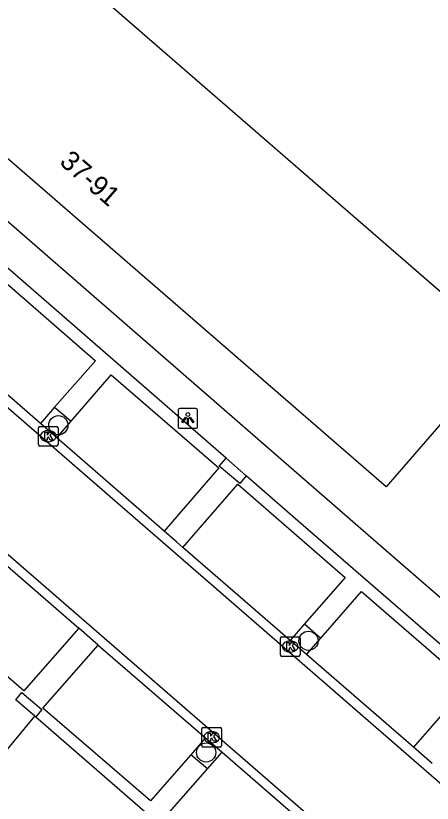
# Model space of a CAD drawing. Extents: x 161882 to 162509, y 381687 to 382379.
# Drawn here: x 162016.16 to 162037.39, y 382160.76 to 382200.83 of the extents above; entities that cross this region are included whole.
import ezdxf

# ---------------------------------------------------------------- set-up
doc = ezdxf.new("R2010")
doc.units = 0
for name, color, linetype in [('IMGEO_Boom', 7, 'Continuous'), ('IMGEO_Kolk', 7, 'Continuous'), ('IMGEO_Lichtpunt', 7, 'Continuous'), ('IMGEO_Pand', 7, 'Continuous'), ('IMGEO_Pand_nummerreeks', 7, 'Continuous'), ('IMGEO_Parkeervlak_open', 7, 'Continuous'), ('IMGEO_Rijbaan_lokaal_open', 7, 'Continuous'), ('IMGEO_Voetpad_op_trap', 7, 'Continuous'), ('IMGEO_Voetpad_open', 7, 'Continuous')]:
    doc.layers.add(name, color=color, linetype=linetype)

msp = doc.modelspace()

# ---------------------------------------------------------------- linework, layer by layer
at = {"layer": 'IMGEO_Boom'}
for centre in [(162018.336, 382179.992), (162031.081, 382169.028), (162025.866, 382163.347)]:
    msp.add_circle(centre, 0.489, dxfattribs=at)
at = {"layer": 'IMGEO_Kolk'}
for p, q in [((162017.317, 382179.01), (162017.317, 382179.862)), ((162017.392, 382179.936), (162018.244, 382179.936)), ((162018.318, 382179.862), (162018.318, 382179.01)), ((162017.805, 382179.716), (162017.83, 382179.716)), ((162017.828, 382179.156), (162017.803, 382179.156)), ((162018.244, 382178.936), (162017.392, 382178.936)), ((162029.647, 382168.31), (162029.647, 382169.162)), ((162029.722, 382169.236), (162030.574, 382169.236)), ((162030.648, 382169.162), (162030.648, 382168.31)), ((162030.135, 382169.016), (162030.16, 382169.016)), ((162030.574, 382168.236), (162029.722, 382168.236)), ((162030.158, 382168.456), (162030.133, 382168.456)), ((162025.719, 382164.62), (162026.571, 382164.62)), ((162025.644, 382163.694), (162025.644, 382164.546)), ((162026.132, 382164.4), (162026.157, 382164.4)), ((162026.645, 382164.546), (162026.645, 382163.694)), ((162026.155, 382163.84), (162026.13, 382163.84)), ((162026.571, 382163.62), (162025.719, 382163.62))]:
    msp.add_line(p, q, dxfattribs=at)
for points in [[(162017.317, 382179.01), (162017.317, 382179.862)], [(162017.392, 382179.936), (162018.244, 382179.936)], [(162018.318, 382179.862), (162018.318, 382179.01)], [(162017.638, 382179.636), (162017.761, 382179.636), (162017.761, 382179.485), (162017.891, 382179.636), (162018.055, 382179.636), (162017.909, 382179.485), (162018.062, 382179.236), (162017.91, 382179.236), (162017.825, 382179.4), (162017.761, 382179.333), (162017.761, 382179.236), (162017.638, 382179.236), (162017.638, 382179.636)], [(162018.244, 382178.936), (162017.392, 382178.936)], [(162029.647, 382168.31), (162029.647, 382169.162)], [(162029.722, 382169.236), (162030.574, 382169.236)], [(162030.648, 382169.162), (162030.648, 382168.31)], [(162029.968, 382168.936), (162030.091, 382168.936), (162030.091, 382168.785), (162030.221, 382168.936), (162030.385, 382168.936), (162030.239, 382168.785), (162030.392, 382168.536), (162030.24, 382168.536), (162030.155, 382168.7), (162030.091, 382168.633), (162030.091, 382168.536), (162029.968, 382168.536), (162029.968, 382168.936)], [(162030.574, 382168.236), (162029.722, 382168.236)], [(162025.719, 382164.62), (162026.571, 382164.62)], [(162025.644, 382163.694), (162025.644, 382164.546)], [(162025.965, 382164.32), (162026.088, 382164.32), (162026.088, 382164.169), (162026.218, 382164.32), (162026.382, 382164.32), (162026.236, 382164.169), (162026.389, 382163.92), (162026.237, 382163.92), (162026.152, 382164.084), (162026.088, 382164.017), (162026.088, 382163.92), (162025.965, 382163.92), (162025.965, 382164.32)], [(162026.645, 382164.546), (162026.645, 382163.694)], [(162026.571, 382163.62), (162025.719, 382163.62)]]:
    msp.add_lwpolyline(points, dxfattribs=at)
for centre, start, end in [((162017.394, 382179.86), 91.552, 178.448), ((162017.394, 382179.86), 91.552, 178.448), ((162018.242, 382179.86), 1.552, 88.448), ((162018.242, 382179.86), 1.552, 88.448), ((162017.394, 382179.012), 181.552, 268.448), ((162017.394, 382179.012), 181.552, 268.448), ((162018.242, 382179.012), 271.552, 358.448), ((162018.242, 382179.012), 271.552, 358.448), ((162029.724, 382169.16), 91.552, 178.448), ((162029.724, 382169.16), 91.552, 178.448), ((162030.572, 382169.16), 1.552, 88.448), ((162030.572, 382169.16), 1.552, 88.448), ((162029.724, 382168.312), 181.552, 268.448), ((162029.724, 382168.312), 181.552, 268.448), ((162030.572, 382168.312), 271.552, 358.448), ((162030.572, 382168.312), 271.552, 358.448), ((162025.721, 382164.544), 91.552, 178.448), ((162025.721, 382164.544), 91.552, 178.448), ((162026.569, 382164.544), 1.552, 88.448), ((162026.569, 382164.544), 1.552, 88.448), ((162025.721, 382163.696), 181.552, 268.448), ((162025.721, 382163.696), 181.552, 268.448), ((162026.569, 382163.696), 271.552, 358.448), ((162026.569, 382163.696), 271.552, 358.448)]:
    msp.add_arc(centre, 0.0765, start, end, dxfattribs=at)
for centre, major_axis, ratio, start_param, end_param in [((162017.804, 382179.436), (-0.387, 0.002), 0.722429, 4.712389, 7.853982), ((162017.829, 382179.436), (-0.39, 0.002), 0.717154, 1.570796, 4.712389), ((162030.134, 382168.736), (-0.387, 0.002), 0.722429, 4.712389, 7.853982), ((162030.159, 382168.736), (-0.39, 0.002), 0.717154, 1.570796, 4.712389), ((162026.131, 382164.12), (-0.387, 0.002), 0.722429, 4.712389, 7.853982), ((162026.156, 382164.12), (-0.39, 0.002), 0.717154, 1.570796, 4.712389)]:
    msp.add_ellipse(centre, major_axis=major_axis, ratio=ratio, start_param=start_param, end_param=end_param, dxfattribs=at)
at = {"layer": 'IMGEO_Lichtpunt'}
for p, q in [((162024.432, 382180.744), (162024.432, 382179.937)), ((162024.432, 382180.744), (162024.432, 382179.937)), ((162025.334, 382180.839), (162024.526, 382180.839)), ((162025.334, 382180.839), (162024.526, 382180.839)), ((162025.428, 382179.937), (162025.428, 382180.744)), ((162025.428, 382179.937), (162025.428, 382180.744)), ((162024.526, 382179.843), (162025.334, 382179.843)), ((162024.526, 382179.843), (162025.334, 382179.843))]:
    msp.add_line(p, q, dxfattribs=at)
for points in [[(162024.806, 382180.408), (162024.845, 382180.38), (162024.657, 382180.118), (162024.619, 382180.145), (162024.806, 382180.408)], [(162024.908, 382180.36), (162024.955, 382180.36), (162024.955, 382180.038), (162024.908, 382180.038), (162024.908, 382180.36)], [(162025.018, 382180.38), (162025.056, 382180.407), (162025.243, 382180.145), (162025.204, 382180.117), (162025.018, 382180.38)]]:
    msp.add_lwpolyline(points, dxfattribs=at)
msp.add_circle((162024.931, 382180.542), 0.0994, dxfattribs=at)
for centre, start, end in [((162024.526, 382180.744), 90, 180), ((162024.526, 382180.744), 90, 180), ((162025.334, 382180.744), 0, 90), ((162025.334, 382180.744), 0, 90), ((162024.526, 382179.937), 180, 270), ((162024.526, 382179.937), 180, 270), ((162025.334, 382179.937), 270, 0), ((162025.334, 382179.937), 270, 360)]:
    msp.add_arc(centre, 0.0946, start, end, dxfattribs=at)
at = {"layer": 'IMGEO_Pand'}
msp.add_lwpolyline([(162010.443, 382210.514), (162014.282, 382207.186), (162018.121, 382203.859), (162041.023, 382184.008), (162041.152, 382183.891), (162035.04, 382176.852), (162004.335, 382203.455)], dxfattribs=at)
at = {"layer": 'IMGEO_Parkeervlak_open'}
for points in [[(162018.145, 382180.908), (162017.419, 382180.08)], [(162018.255, 382179.355), (162018.982, 382180.193)], [(162030.882, 382169.882), (162030.15, 382169.045)], [(162030.974, 382168.332), (162031.705, 382169.163)], [(162025.835, 382164.089), (162025.078, 382163.223)], [(162025.936, 382162.505), (162026.682, 382163.354)]]:
    msp.add_lwpolyline(points, dxfattribs=at)
at = {"layer": 'IMGEO_Rijbaan_lokaal_open'}
for points in [[(162004.578, 382191.195), (162004.274, 382190.846), (162005.488, 382189.784), (162024.055, 382173.714), (162042.512, 382157.689)], [(162036.646, 382154.691), (162036.967, 382155.028), (162001.899, 382185.403), (162000.705, 382186.422), (162000.438, 382186.65), (162000.135, 382186.301)], [(162017.419, 382180.08), (162011.989, 382184.789)], [(162018.255, 382179.355), (162017.419, 382180.08)], [(162023.729, 382174.608), (162018.255, 382179.355)], [(162013.934, 382174.385), (162019.379, 382169.666)], [(162024.683, 382173.78), (162024.348, 382174.07), (162023.729, 382174.608)], [(162030.15, 382169.045), (162024.683, 382173.78)], [(162020.364, 382168.811), (162019.379, 382169.666)], [(162030.974, 382168.332), (162030.15, 382169.045)], [(162020.364, 382168.811), (162025.835, 382164.089)], [(162036.426, 382163.61), (162030.974, 382168.332)], [(162025.835, 382164.089), (162026.682, 382163.354)], [(162037.387, 382162.778), (162036.426, 382163.61)], [(162026.682, 382163.354), (162032.109, 382158.646)]]:
    msp.add_lwpolyline(points, dxfattribs=at)
at = {"layer": 'IMGEO_Voetpad_op_trap'}
msp.add_lwpolyline([(162017.138, 382165.198), (162017.182, 382165.16)], dxfattribs=at)
at = {"layer": 'IMGEO_Voetpad_open'}
for points in [[(162002.15, 382202.152), (162007.715, 382197.353), (162034.901, 382173.742), (162058.69, 382153.142), (162067.845, 382145.177), (162076.705, 382137.459), (162080.965, 382142.814), (162080.908, 382142.859)], [(162026.877, 382178.317), (162015.213, 382188.449)], [(162011.989, 382184.789), (162014.78, 382188.011), (162020.22, 382183.275), (162018.145, 382180.908)], [(162018.982, 382180.193), (162021.034, 382182.559), (162026.506, 382177.825), (162023.729, 382174.608)], [(162018.145, 382180.908), (162018.982, 382180.193)], [(162027.903, 382177.426), (162027.579, 382177.037), (162026.535, 382177.905), (162026.877, 382178.317)], [(162026.877, 382178.317), (162027.903, 382177.426)], [(162039.593, 382167.298), (162030.56, 382175.118), (162027.903, 382177.426)], [(162024.683, 382173.78), (162027.479, 382176.996), (162032.954, 382172.25), (162030.882, 382169.882)], [(162019.379, 382169.666), (162016.581, 382166.476), (162011.116, 382171.188), (162013.2, 382173.552)], [(162031.705, 382169.163), (162033.785, 382171.53), (162039.223, 382166.817), (162036.426, 382163.61)], [(162030.882, 382169.882), (162031.705, 382169.163)], [(162025.078, 382163.223), (162023.028, 382160.878), (162017.537, 382165.601), (162020.364, 382168.811)], [(162016.175, 382166.031), (162016.48, 382166.39), (162017.495, 382165.528), (162017.182, 382165.16)], [(162016.152, 382166.051), (162016.175, 382166.031)], [(162017.138, 382165.198), (162016.175, 382166.031)], [(162028.853, 382155.032), (162024.17, 382149.745), (162014.005, 382161.432), (162017.138, 382165.198)], [(162017.182, 382165.16), (162028.853, 382155.032)], [(162025.936, 382162.505), (162025.078, 382163.223)], [(162032.109, 382158.646), (162029.293, 382155.466), (162023.868, 382160.155), (162025.936, 382162.505)]]:
    msp.add_lwpolyline(points, dxfattribs=at)

# ---------------------------------------------------------------- texts
at = {"layer": 'IMGEO_Pand_nummerreeks'}
msp.add_text('37-91', height=1, rotation=318.896, dxfattribs=at).set_placement((162018.343, 382193.313))

doc.saveas('drawing.dxf')
